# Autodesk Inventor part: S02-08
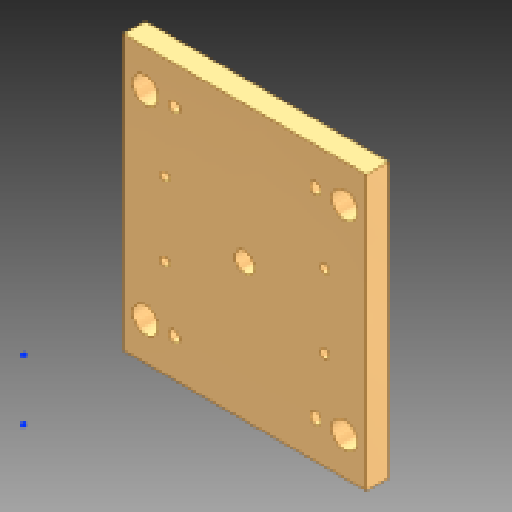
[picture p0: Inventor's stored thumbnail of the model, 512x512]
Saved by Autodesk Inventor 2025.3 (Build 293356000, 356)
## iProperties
Created: 2025-04
Part Number: S02-08
Material: Všeobecné
Document SubType Name: Modeling
Designer: Patrik
Density: 1 g/cm^3
Appearance: Výchozí
Description: Deska opěrná levá
Stock Number: F 10 /396 396/ 36/1730
Mass: 6031.71 g
Surface Area: 4389.05 cm^2
Volume: 6031.71 cm^3
User Status: 1730
Author: Patrik
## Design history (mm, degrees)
feature "Base1"
feature "Vyřezání2"
feature "Vyřezání3"
sketch "Náčrt1"
  geometry: C1 r 16 at (0, 0) reference; 1 further point
extrude "Vysunutí1" cut sketch "Náčrt1" stored distance "d0" = 10; taper "d1" = 0 deg
feature "Vyřezání7"
sketch "Náčrt5"
  geometry: C1 r 2.46 at (68, -286.97) reference; C2 r 2.46 at (328, -286.97) reference; C3 r 2.46 at (68, -166.97) reference; C4 r 2.46 at (328, -166.97) reference; 1 further point
extrude "Vysunutí5" cut sketch "Náčrt5" stored distance "d8" = 10; taper "d9" = 0 deg
sketch "Náčrt6"
  geometry: C1 r 3.26 at (68, 159.03) reference; C2 r 5 at (68, 159.03) reference; C3 r 3.26 at (328, 159.03) reference; C4 r 5 at (328, 159.03) reference; C5 r 3.26 at (328, 279.03) reference; C6 r 5 at (328, 279.03) reference; C7 r 3.26 at (68, 279.03) reference; C8 r 5 at (68, 279.03) reference; 1 further point
extrude "Vysunutí6" cut sketch "Náčrt6" stored distance "d10" = 10; taper "d11" = 0 deg
feature "Vyřezání8"
sketch "Náčrt7"
  geometry: C1 r 8 at (-18, 223) reference; 1 further point
hole "Díra1" sketch "Náčrt7" at (-18, 223) diameter "d12" = 13.835; stored, may be unused: countersink angle "d16" = 89.9544 deg, drill point angle "d18" = 118 deg; dims "d13" = 20, "d14" = 33, "d15" = 8.6, "d17" = 25
chamfer "Zkosení1" distance "d19" = 1; stored, may be unused: second distance "d20" = 2, angle "d21" = 45 deg
sketch "Náčrt8"
  geometry: C1 r 3 at (376, 426) reference; C2 r 3 at (376, 20) reference; C3 r 3 at (198, 20) reference; C4 r 3 at (20, 20) reference; C5 r 3 at (20, 426) reference; C6 r 3 at (198, 426) reference; 1 further point
hole "Díra2" sketch "Náčrt8" at (376, 426), (198, 426), (20, 426), (20, 20), (198, 20), (376, 20) diameter "d22" = 4.917; stored, may be unused: countersink angle "d26" = 90 deg, drill point angle "d28" = 118 deg; dims "d23" = 5, "d24" = 4, "d25" = 2, "d27" = 8
feature "Vyřezání9"
sketch "Náčrt9"
  geometry: A1 r 3 centre (198.709, 271.995) between (198.389, 269.012) and (198.44, 274.983) reference; A2 r 3 centre (197.88, 174) between (197.56, 171.017) and (197.611, 176.988) reference; 1 further point
hole "Díra3" sketch "Náčrt9" at (197.88, 174), (198.709, 271.995) diameter "d29" = 4.917; stored, may be unused: countersink angle "d33" = 90 deg, drill point angle "d35" = 118 deg; dims "d30" = 2, "d31" = 4, "d32" = 2, "d34" = 5
node "Těleso1"
node "Referenční1"
node "Promítnutá smyčka2"
node "Promítnutá smyčka3"
node "Promítnutá smyčka4"
node "Promítnutá smyčka5"
feature "Plocha2"
node "Povrch2"
feature "Plocha3"
node "Povrch3"
feature "Plocha11"
node "Povrch11"
feature "Plocha12"
node "Povrch12"
feature "Plocha13"
node "Povrch13"
